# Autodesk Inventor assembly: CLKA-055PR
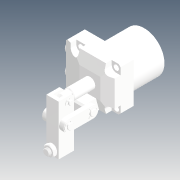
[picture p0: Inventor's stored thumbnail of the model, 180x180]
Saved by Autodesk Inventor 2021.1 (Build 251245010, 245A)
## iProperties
Created: 2019-04
Part Number: CLKA-055PR
Description: STEP AP214
Document SubType Name: Assembly
Designer: user
Title: CLKA-055P-R.STEP
Revision Number: ÈÎºÎ
Sending System: SolidWorks 2016
Preprocessor: SwSTEP 2.0
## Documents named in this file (12)
- D:\Vault_2016\Projekty\Clamptek\Hydraulic\CLKA-P\Inventor\CLKA-055PR\CLKA-055PR.iam
- D:\Vault_2016\Projekty\Clamptek\Hydraulic\CLKA-P\Inventor\CLKA-055PR\CLKA-055P-R-benti.ipt
- D:\Vault_2016\Projekty\Clamptek\Hydraulic\CLKA-P\Inventor\CLKA-055PR\6MM¿ª¿Úµ²È¦.ipt
- D:\Vault_2016\Projekty\Clamptek\Hydraulic\CLKA-P\Inventor\CLKA-055PR\8MMdangjuan.ipt
- D:\Vault_2016\Projekty\Clamptek\Hydraulic\CLKA-P\Inventor\CLKA-055PR\duanxiao.ipt
- D:\Vault_2016\Projekty\Clamptek\Hydraulic\CLKA-P\Inventor\CLKA-055PR\huosaigan.ipt
- D:\Vault_2016\Projekty\Clamptek\Hydraulic\CLKA-P\Inventor\CLKA-055PR\liangan.ipt
- D:\Vault_2016\Projekty\Clamptek\Hydraulic\CLKA-P\Inventor\CLKA-055PR\luosi.ipt
- D:\Vault_2016\Projekty\Clamptek\Hydraulic\CLKA-P\Inventor\CLKA-055PR\M8luomu.ipt
- D:\Vault_2016\Projekty\Clamptek\Hydraulic\CLKA-P\Inventor\CLKA-055PR\yabi.ipt
- D:\Vault_2016\Projekty\Clamptek\Hydraulic\CLKA-P\Inventor\CLKA-055PR\zhangxiao.ipt
- D:\Vault_2016\Projekty\Clamptek\Hydraulic\CLKA-P\Inventor\CLKA-055PR\¶ÂÍ·G8-1.ipt
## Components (18 placed, 18 different names)
1. CLKA-055P-R-benti_1
2. 6MM¿ª¿Úµ²È¦_2
3. 8MMdangjuan_3
4. duanxiao_4
5. huosaigan_5
6. liangan_6
7. luosi_7
8. M8luomu_8
9. yabi_9
10. zhangxiao_10
11. liangan_11
12. zhangxiao_12
13. 6MM¿ª¿Úµ²È¦_13
14. 8MMdangjuan_14
15. 8MMdangjuan_15
16. 8MMdangjuan_16
17. ¶ÂÍ·G8-1_17
18. ¶ÂÍ·G8-1_18
